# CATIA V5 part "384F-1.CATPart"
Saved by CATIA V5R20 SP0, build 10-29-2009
Part number: 384F-1
Source: Unknown
Property "ARTICLENO": "384F-1"
Property "BOMINFO": "384F-1"
Property "CODE": "384F-1"
Property "CREATOR": "CADENAS GmbH"
Property "D1": "19.000"
Property "D2": "28.000"
Property "ELASTOMER": "Ø63"
Property "K": "17.000"
Property "L": "56.000"
Property "L1": "8.000"
Property "L2": "26.000"
Property "LINA": "384F-1"
Property "M": "12.000"
Property "NB": "384F-1"
Property "NBSYN": "$CODE."
Property "NN": "384F"
Property "NT": "Pin for Elastomer Springs"
Property "R": "4.500"
Property "SUPPLIER": "CF"
Property "SW": "6.000"
Bounding box of the stored display mesh (mm): x -12.936 to 12.936, y 0 to 56, z -13.069 to 13.069
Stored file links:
  C:\Users\Raffaele\Desktop\3D X SITO CF\384F\GSB_OILLESS_M31102012056\CATIAV5\384F-1.CATPart
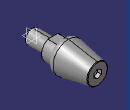
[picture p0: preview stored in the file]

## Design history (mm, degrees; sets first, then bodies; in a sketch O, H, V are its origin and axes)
Body1 "Geometry.1" (main body)
  Solid1 "384F-1.catpart": solid without history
